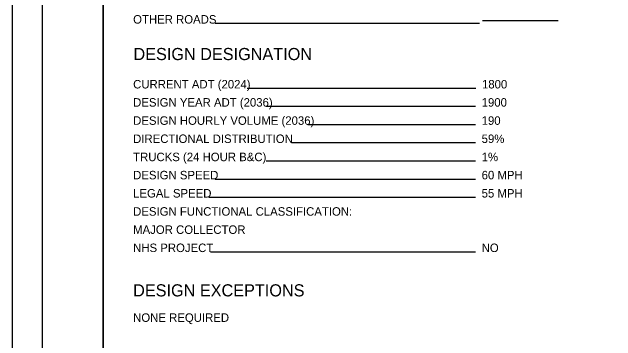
# Model space of a CAD drawing. Extents: x 36.7 to 70.7, y 0 to 22.
# Drawn here: x 36.69 to 46.64, y 5.64 to 11.06 of the extents above; entities that cross this region are included whole.
import ezdxf

# ---------------------------------------------------------------- set-up
doc = ezdxf.new("R2010")
doc.units = 0
for name, color, linetype in [('SH_Border', 7, 'Continuous'), ('SH_Cut_Line', 7, 'Continuous'), ('SH_Data', 7, 'Continuous'), ('SH_Text', 7, 'Continuous')]:
    doc.layers.add(name, color=color, linetype=linetype)

msp = doc.modelspace()

# ---------------------------------------------------------------- linework, layer by layer
at = {"layer": 'SH_Border'}
for points in [[(37.1934, 21.4969), (38.1934, 21.4969), (38.1934, 0.4969), (37.1934, 0.4969)], [(38.1934, 21.4969), (70.1934, 21.4969), (70.1934, 0.4969), (38.1934, 0.4969)]]:
    msp.add_lwpolyline(points, close=True, dxfattribs=at)
at = {"layer": 'SH_Cut_Line'}
msp.add_lwpolyline([(36.6934, -0.0031), (70.6934, -0.0031), (70.6934, 21.9969), (36.6934, 21.9969)], close=True, dxfattribs=at)
at = {"layer": 'SH_Data'}
for p, q in [((44.3934, 10.8736), (40.0405, 10.8736)), ((45.6934, 10.9192), (44.4434, 10.9192)), ((44.3358, 9.8032), (40.5644, 9.8032)), ((44.3302, 9.5032), (40.8819, 9.5032)), ((44.3302, 9.2032), (41.5657, 9.2032)), ((44.3302, 8.9032), (41.2971, 8.9032)), ((44.3302, 8.6032), (40.8819, 8.6032)), ((44.3302, 8.3032), (40.0394, 8.3032)), ((44.3302, 8.0032), (39.9356, 8.0032)), ((44.3302, 7.1032), (39.9603, 7.1032))]:
    msp.add_line(p, q, dxfattribs=at)

# ---------------------------------------------------------------- texts
msp.add_text('DESIGN DESIGNATION', height=0.2, dxfattribs=at).set_placement((38.6934, 10.2716))
at = {"layer": 'SH_Text'}
for s, height, p in [('OTHER ROADS', 0.14, (38.6878, 10.8736)), ('CURRENT ADT (2024)', 0.14, (38.6878, 9.8032)), ('1800', 0.14, (44.4358, 9.8032)), ('DESIGN YEAR ADT (2036)', 0.14, (38.6878, 9.5032)), ('1900', 0.14, (44.4302, 9.5032)), ('DESIGN HOURLY VOLUME (2036)', 0.14, (38.6878, 9.2032)), ('190', 0.14, (44.4302, 9.2032)), ('DIRECTIONAL DISTRIBUTION', 0.14, (38.6878, 8.9032)), ('59%', 0.14, (44.4302, 8.9032)), ('TRUCKS (24 HOUR B&C)', 0.14, (38.6878, 8.6032)), ('1%', 0.14, (44.4302, 8.6032)), ('DESIGN SPEED', 0.14, (38.6878, 8.3032)), ('60 MPH', 0.14, (44.4302, 8.3032)), ('LEGAL SPEED', 0.14, (38.6878, 8.0032)), ('55 MPH', 0.14, (44.4302, 8.0032)), ('DESIGN FUNCTIONAL CLASSIFICATION:', 0.14, (38.6878, 7.7032)), ('MAJOR COLLECTOR', 0.14, (38.6878, 7.4032)), ('NHS PROJECT', 0.14, (38.6878, 7.1032)), ('NO', 0.14, (44.4302, 7.1032)), ('DESIGN EXCEPTIONS', 0.2, (38.6878, 6.3713)), ('NONE REQUIRED', 0.14, (38.6878, 5.9513))]:
    msp.add_text(s, height=height, dxfattribs=at).set_placement(p)

doc.saveas('drawing.dxf')
